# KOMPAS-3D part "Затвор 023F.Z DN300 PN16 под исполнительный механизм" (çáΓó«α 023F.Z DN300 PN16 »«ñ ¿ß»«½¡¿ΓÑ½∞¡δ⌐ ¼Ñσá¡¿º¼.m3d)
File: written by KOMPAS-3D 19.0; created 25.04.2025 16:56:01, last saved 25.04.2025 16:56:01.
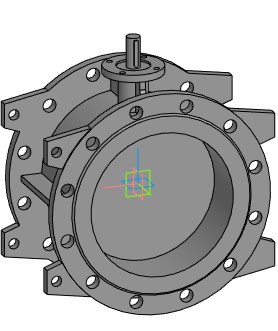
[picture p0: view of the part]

Document properties: Автор: Евгений; Полное имя файла: E:\Dendor Работа Сачек\3D для проекитирвщиков\1.7 Тип 023F.Z Затвор дисковый поворотный фланцевый с двумя эксцентриками\stp_Тип 023F.Z. Затвор под исполн. механизм\Затвор 023F.Z DN300 PN16 под исполнительный механизм.m3d

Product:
- Part/product: Затвор 023F.Z DN300 PN16 под исполнительный механизм

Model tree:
1. Операция без истории:1  (labels: Затвор 023F.Z DN300 PN16 под исполнительный механизм)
